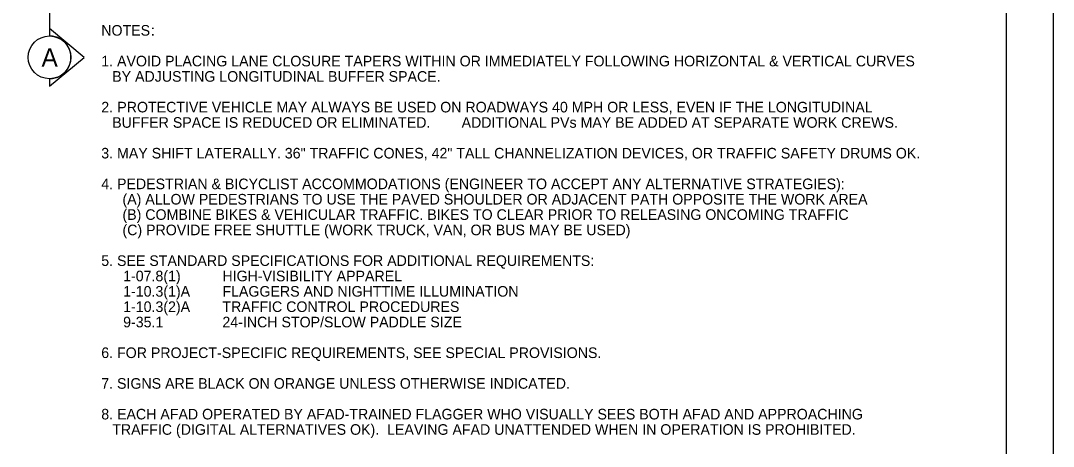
# Model space of a CAD drawing. Extents: x 99999.1 to 100095.7, y 99995 to 100010.7.
# Drawn here: x 100009.24 to 100016.06, y 100002.81 to 100005.62 of the extents above; entities that cross this region are included whole.
import ezdxf

# ---------------------------------------------------------------- set-up
doc = ezdxf.new("R2010")
doc.units = 0
for name, color, linetype in [('SH_GI_GeneralNotesBodyText', 7, 'Continuous'), ('SH_GI_PlotLimits', 7, 'Continuous'), ('SH_GI_SheetBorder', 7, 'Continuous'), ('SH_TI_WZSectionCut', 7, 'Continuous')]:
    doc.layers.add(name, color=color, linetype=linetype)

msp = doc.modelspace()

# ---------------------------------------------------------------- linework, layer by layer
at = {"layer": 'SH_GI_PlotLimits'}
msp.add_lwpolyline([(99999.0625, 99999.6875), (100016.0625, 99999.6875), (100016.0625, 100010.6875), (99999.0625, 100010.6875)], close=True, dxfattribs=at)
at = {"layer": 'SH_GI_SheetBorder'}
msp.add_line((100015.75, 100010.375), (100015.75, 100000), dxfattribs=at)
at = {"layer": 'SH_TI_WZSectionCut'}
for p, q in [((100009.4338, 100007.7022), (100009.4338, 100005.5723)), ((100009.4337, 100005.5723), (100009.4337, 100005.5224)), ((100009.6619, 100005.3812), (100009.4337, 100005.5723)), ((100009.4337, 100005.1901), (100009.6619, 100005.3812)), ((100009.4337, 100005.24), (100009.4337, 100005.1901))]:
    msp.add_line(p, q, dxfattribs=at)
msp.add_circle((100009.4338, 100005.3812), 0.1412, dxfattribs=at)
msp.add_arc((100009.4338, 100005.3812), 0.1412, 269.99779, 90.00221, dxfattribs=at)

# ---------------------------------------------------------------- texts
at = {"layer": 'SH_GI_GeneralNotesBodyText'}
for s, p in [('NOTES', (100009.7751, 100005.5246)), (':', (100010.1026, 100005.5246)), ('1. AVOID PLACING LANE CLOSURE TAPERS WITHIN OR IMMEDIATELY FOLLOWING HORIZONTAL & VERTICAL CURVES ', (100009.7751, 100005.3216)), ('BY ADJUSTING LONGITUDINAL BUFFER SPACE.', (100009.8473, 100005.2201)), ('2. ', (100009.7751, 100005.0171)), ('PROTECTIVE VEHICLE MAY ALWAYS BE USED ON ROADWAYS 40 MPH OR LESS, EVEN IF THE LONGITUDINAL ', (100009.8808, 100005.0171)), ('BUFFER SPACE IS REDUCED OR ELIMINATED.', (100009.8473, 100004.9156)), ('  ADDITIONAL PVs MAY BE ADDED AT SEPARATE WORK CREWS.', (100012.1026, 100004.9156)), ('3. MAY SHIFT LATERALLY. 36" TRAFFIC CONES, 42" TALL CHANNELIZATION DEVICES, OR TRAFFIC SAFETY DRUMS OK.', (100009.7751, 100004.7126)), ('4. PEDESTRIAN & BICYCLIST ACCOMMODATIONS (ENGINEER TO ACCEPT ANY ALTERNATIVE STRATEGIES):', (100009.7751, 100004.5096)), ('(A) ALLOW PEDESTRIANS TO USE THE PAVED SHOULDER OR ADJACENT PATH OPPOSITE THE WORK AREA', (100009.9151, 100004.4081)), ('(B) COMBINE BIKES & VEHICULAR TRAFFIC. BIKES TO CLEAR PRIOR TO RELEASING ONCOMING TRAFFIC', (100009.9151, 100004.3066)), ('(C) PROVIDE FREE SHUTTLE (WORK TRUCK, VAN, OR BUS MAY BE USED)', (100009.9151, 100004.2051)), ('5. SEE STANDARD SPECIFICATIONS FOR ADDITIONAL REQUIREMENTS:', (100009.7751, 100004.0021)), ('1-07.8(1) ', (100009.9195, 100003.9006)), ('HIGH-VISIBILITY APPAREL', (100010.5751, 100003.9006)), ('1-10.3(1)A ', (100009.9195, 100003.7991)), ('FLAGGERS AND NIGHTTIME ILLUMINATION', (100010.5751, 100003.7991)), ('1-10.3(2)A', (100009.9195, 100003.6976)), ('TRAFFIC CONTROL PROCEDURES', (100010.5751, 100003.6976)), ('9-35.1', (100009.9195, 100003.5961)), ('24-INCH STOP/SLOW PADDLE SIZE', (100010.5751, 100003.5961)), ('6. FOR PROJECT-SPECIFIC REQUIREMENTS, SEE SPECIAL PROVISIONS.', (100009.7751, 100003.3931)), ('7. SIGNS ARE BLACK ON ORANGE UNLESS OTHERWISE INDICATED.', (100009.7751, 100003.1901)), ('8. EACH AFAD OPERATED BY AFAD-TRAINED FLAGGER WHO VISUALLY SEES BOTH AFAD AND APPROACHING ', (100009.7751, 100002.9871)), ('TRAFFIC (DIGITAL ALTERNATIVES OK).  LEAVING AFAD UNATTENDED WHEN IN OPERATION IS PROHIBITED.', (100009.8473, 100002.8856))]:
    msp.add_text(s, height=0.07, rotation=360, dxfattribs=at).set_placement(p)
at = {"layer": 'SH_TI_WZSectionCut'}
msp.add_text('A', height=0.12, rotation=0.00995, dxfattribs=at).set_placement((100009.3808, 100005.3203))

doc.saveas('drawing.dxf')
